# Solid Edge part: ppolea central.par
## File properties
Author: there
Template: iso metric part.par
Last saved by: there
Revision: 3
Application: Solid Edge
Precisión: 0.990
Username: there
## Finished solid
Body 1: solid body, 12 faces, 12 edges, 0 vertices.
  Faces by surface: cylinder 6, plane 6
  Edges by curve: circle 12
Bounding box of the edges (mm): 52.000 x 23.000 x 52.000, from (-26, -13, -26) to (26, 10, 26).
Cylindrical faces by radius (mm): R3.2 x1, R12.5 x1, R16 x1, R25 x1, R26 x2
Planar faces by outward normal: +y 3, -y 3
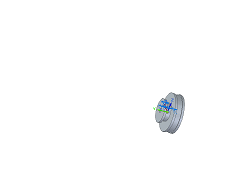
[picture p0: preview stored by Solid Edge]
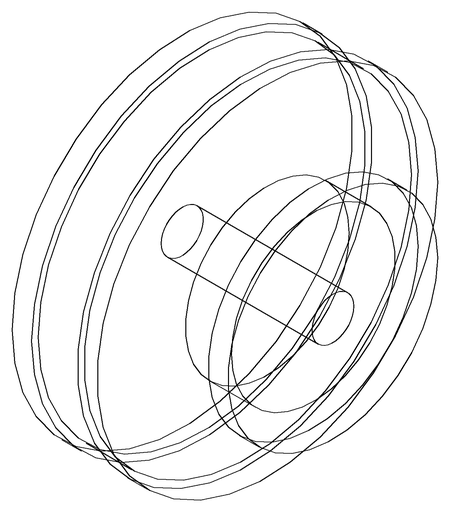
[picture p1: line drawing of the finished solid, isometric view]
